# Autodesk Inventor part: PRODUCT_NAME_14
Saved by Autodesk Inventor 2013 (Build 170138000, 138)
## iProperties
Created: 2012-12
Part Number: PRODUCT_NAME_14
Material: Générique
Document SubType Name: Modeling
Designer: jost thierry
Density: 1 g/cm^3
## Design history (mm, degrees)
node "PRODUCT_NAME_141"
node "PRODUCT_NAME_14"
node "Base1"
